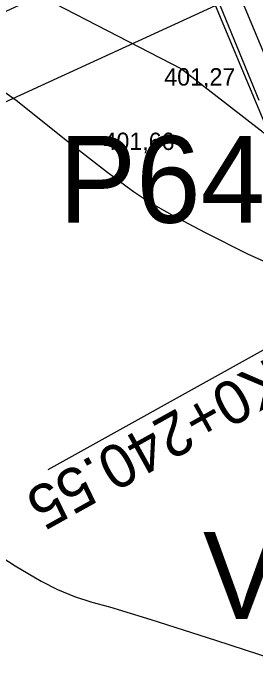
# Model space of a CAD drawing. Extents: x -574342 to -507939, y -1144044 to -1123894.
# Drawn here: x -508545.96 to -508532.02, y -1143301.62 to -1143262.87 of the extents above; entities that cross this region are included whole.
import ezdxf

# ---------------------------------------------------------------- set-up
doc = ezdxf.new("R2010")
doc.units = 0
for name, color, linetype in [('01_PARCELY_NAVRH_VHO', 7, 'Continuous'), ('01_PARCELY_NAVRH_ŽP', 7, 'Continuous'), ('03_PC_OBJEKTY_POP_NAVRH', 7, 'Continuous'), ('1000', 7, 'Continuous'), ('18', 7, 'Continuous'), ('21', 7, 'Continuous'), ('23', 7, 'Continuous'), ('42', 7, 'Continuous'), ('Level 255', 7, 'Continuous'), ('VRST VEDL', 7, 'Continuous')]:
    doc.layers.add(name, color=color, linetype=linetype)

msp = doc.modelspace()

# ---------------------------------------------------------------- linework, layer by layer
at = {"layer": '01_PARCELY_NAVRH_VHO'}
msp.add_lwpolyline([(-508497.13, -1143495.86), (-508497.34, -1143500.64), (-508499.94, -1143496.07), (-508501.52, -1143472.9), (-508509.71, -1143373.98), (-508513.61, -1143343.97), (-508516.21, -1143324.53), (-508518.91, -1143309.47), (-508522.63, -1143293.85), (-508527.23, -1143279.34), (-508534.32, -1143262.4), (-508535.36, -1143259.89), (-508531.94, -1143260.32), (-508524.61, -1143277.77), (-508522.34, -1143283.22), (-508517.78, -1143295.12), (-508517.67, -1143298.65), (-508514.79, -1143310.81), (-508512.2, -1143325.42), (-508505.85, -1143384.53), (-508502.4, -1143424.77), (-508500.25, -1143457.08), (-508499.28, -1143468.17)], close=True, dxfattribs=at)
at = {"layer": '01_PARCELY_NAVRH_ŽP'}
msp.add_lwpolyline([(-508866.763, -1143539.171), (-508855.34, -1143520.06), (-508806.85, -1143435.07), (-508768.48, -1143388.71), (-508762.18, -1143383.5), (-508664.92, -1143322.31), (-508534.32, -1143262.4), (-508535.36, -1143259.89), (-508539, -1143259.35), (-508664.99, -1143316.89), (-508766.4, -1143380.31), (-508773.29, -1143386.75), (-508810.66, -1143431.99), (-508859.41, -1143516.97), (-508866.763, -1143529.283)], dxfattribs=at)
at = {"layer": '1000'}
msp.add_lwpolyline([(-508531.803, -1143267.874), (-508534.032, -1143262.444)], dxfattribs=at)
at = {"layer": '21'}
msp.add_lwpolyline([(-508530.606, -1143267.376), (-508532.858, -1143261.956)], dxfattribs=at)
at = {"layer": '23'}
msp.add_lwpolyline([(-508520.39, -1143276.032), (-508543.99, -1143289.148)], dxfattribs=at)
at = {"layer": '42'}
msp.add_lwpolyline([(-508654.2, -1143191.6), (-508651.11, -1143191.46), (-508646.05, -1143192.58), (-508613.56, -1143216.76), (-508566.08, -1143248.87), (-508547.92, -1143260.05), (-508536.29, -1143266.06), (-508529.87, -1143271.02), (-508526.62, -1143279.23), (-508525.63, -1143286.24)], dxfattribs=at)
msp.add_lwpolyline([(-508654.2, -1143191.6), (-508651.11, -1143191.46), (-508646.05, -1143192.58), (-508613.56, -1143216.76), (-508566.08, -1143248.87), (-508547.92, -1143260.05), (-508536.29, -1143266.06), (-508529.87, -1143271.02), (-508526.62, -1143279.23), (-508525.63, -1143286.24)], dxfattribs=at)
at = {"layer": 'VRST VEDL'}
for points in [[(-508530.201, -1143277.747), (-508532.458, -1143276.721), (-508534.9, -1143275.495), (-508536.811, -1143274.491), (-508538.191, -1143273.708), (-508539.041, -1143273.146), (-508540.595, -1143271.988), (-508542.852, -1143270.233), (-508545.813, -1143267.883), (-508549.576, -1143265.241)], [(-508547.924, -1143293.351), (-508545.858, -1143294.667), (-508544.357, -1143295.56), (-508543.421, -1143296.03), (-508542.453, -1143296.432), (-508541.453, -1143296.766), (-508540.422, -1143297.032), (-508538.046, -1143297.759), (-508534.326, -1143298.948), (-508529.261, -1143300.599), (-508525.463, -1143301.902)]]:
    msp.add_lwpolyline(points, dxfattribs=at)

# ---------------------------------------------------------------- texts
at = {"layer": '03_PC_OBJEKTY_POP_NAVRH'}
for s, p in [('P64', (-508543.358, -1143274.917)), ('V15', (-508535.046, -1143297.724))]:
    msp.add_text(s, height=5, dxfattribs=at).set_placement(p)
at = {"layer": '18'}
msp.add_text('TK0+240.55', height=2.5, rotation=209.0636, dxfattribs=at).set_placement((-508529.429, -1143281.628))
at = {"layer": 'Level 255'}
for s, p in [('401,27', (-508537.275, -1143267.02)), ('401,66', (-508540.775, -1143270.73))]:
    msp.add_text(s, height=1, dxfattribs=at).set_placement(p)

doc.saveas('drawing.dxf')
